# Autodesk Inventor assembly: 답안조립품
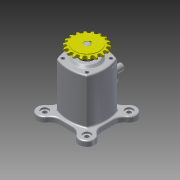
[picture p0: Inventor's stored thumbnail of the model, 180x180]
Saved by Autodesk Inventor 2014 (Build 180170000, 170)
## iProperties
Created: 2016-05
Part Number: 답안조립품
Document SubType Name: Assembly
Designer: user
Author: user
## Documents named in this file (11)
- C:\Users\user\Desktop\460508V1015\답안조립품.iam
- C:\Users\user\Desktop\460508V1015\본체.ipt
- C:\Users\user\Desktop\460508V1015\커버.ipt
- C:\Users\user\Desktop\460508V1015\편심축.ipt
- C:\Users\user\Desktop\460508V1015\키5x5.ipt
- C:\Users\user\Desktop\460508V1015\스프로킷.ipt
- C:\Users\user\Desktop\460508V1015\오일실.ipt
- C:\Users\user\Desktop\460508V1015\베어링-6203.ipt
- C:\Users\user\Desktop\460508V1015\부시.ipt
- C:\Users\user\Desktop\460508V1015\슬라이더.ipt
- C:\Users\user\Desktop\460508V1015\M4x0.7x12.ipt
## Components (8 placed, 1 different names)
1. M4x0.7x12:1 — Insert:11
2. M4x0.7x12:3
3. M4x0.7x12:4
4. M4x0.7x12:5
5. M4x0.7x12:2 — Insert:12
6. M4x0.7x12:6
7. M4x0.7x12:7
8. M4x0.7x12:8
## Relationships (2: Insert 2)
- Insert:11: M4x0.7x12:1
- Insert:12: M4x0.7x12:2
